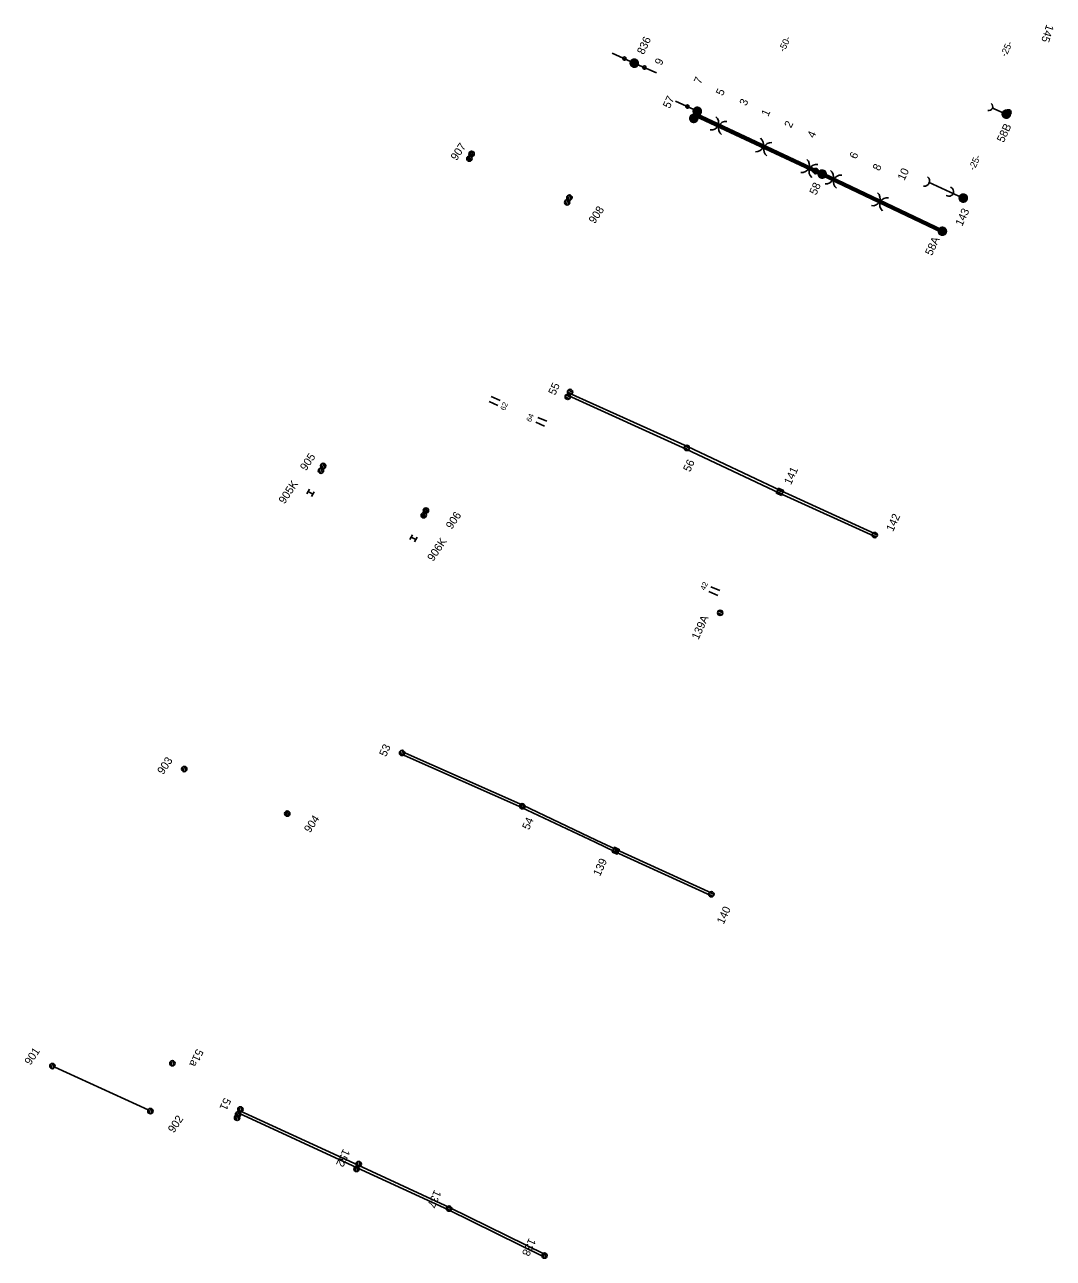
# Model space of a CAD drawing. Extents: x -595867 to -593796, y -1159595 to -1157495.
# Drawn here: x -595001.3 to -594808.6, y -1158560.8 to -1158329.6 of the extents above; entities that cross this region are included whole.
import ezdxf

# ---------------------------------------------------------------- set-up
doc = ezdxf.new("R2010")
doc.units = 0
for name, color, linetype in [('BVK_kanalizace_destova_nova', 7, 'Continuous'), ('BVK_kanalizace_jednotna_nova', 7, 'Continuous'), ('DKM19', 7, 'Continuous'), ('SO31_06_54_1-protlak', 7, 'Continuous')]:
    doc.layers.add(name, color=color, linetype=linetype)

# ---------------------------------------------------------------- blocks, each defined once
blk = doc.blocks.new('st_2t')
for points in [[(-0.0077, 0.0091), (0.0015, 0.0147), (0.0025, 0.0144), (-0.0078, 0.0082)], [(-0.0078, 0.0082), (0.0025, 0.0144), (0.0032, 0.014), (-0.0078, 0.0072)], [(-0.0078, 0.0072), (0.0032, 0.014), (0.004, 0.0135), (-0.0078, 0.0065)], [(-0.0078, 0.0065), (0.004, 0.0135), (0.0048, 0.0129), (-0.0076, 0.0056)], [(-0.0075, 0.0097), (0.0002, 0.0149), (0.0015, 0.0147), (-0.0077, 0.0091)], [(-0.0076, 0.0056), (0.0048, 0.0129), (0.0055, 0.0121), (-0.0073, 0.0044)], [(-0.0073, 0.0104), (-0.0005, 0.015), (0.0002, 0.0149), (-0.0075, 0.0097)], [(-0.0071, 0.0108), (-0.0019, 0.0148), (-0.0005, 0.015), (-0.0073, 0.0104)], [(-0.0073, 0.0044), (0.0055, 0.0121), (0.0063, 0.0109), (-0.0068, 0.0036)], [(-0.0066, 0.0115), (-0.0026, 0.0146), (-0.0019, 0.0148), (-0.0071, 0.0108)], [(-0.0068, 0.0036), (0.0063, 0.0109), (0.0067, 0.0097), (-0.006, 0.0026)], [(-0.0062, 0.0122), (-0.0035, 0.0142), (-0.0026, 0.0146), (-0.0066, 0.0115)], [(-0.0056, 0.0128), (-0.0045, 0.0137), (-0.0035, 0.0142), (-0.0062, 0.0122)], [(-0.006, 0.0026), (0.0067, 0.0097), (0.007, 0.0086), (-0.0052, 0.0018)], [(-0.0052, 0.0018), (0.007, 0.0086), (0.0071, 0.0071), (-0.0044, 0.0012)], [(-0.0044, 0.0012), (0.0071, 0.0071), (0.0069, 0.0057), (-0.0035, 0.0007)], [(-0.0035, 0.0007), (0.0069, 0.0057), (0.0066, 0.0047), (-0.0024, 0.0003)], [(-0.0024, 0.0003), (0.0066, 0.0047), (0.0061, 0.0038), (-0.0015, 0.0001)], [(-0.0015, 0.0001), (0.0061, 0.0038), (0.0055, 0.0029), (-0.0009, 0)], [(-0.0009, 0), (0.0055, 0.0029), (0.005, 0.0022), (0, 0)], [(0, 0), (0.005, 0.0022), (0.0041, 0.0015), (0.001, 0.0001)], [(0.001, 0.0001), (0.0041, 0.0015), (0.0035, 0.001), (0.0021, 0.0004)], [(0.0021, 0.0004), (0.0035, 0.001), (0.0026, 0.0006), (0.0026, 0.0005)], [(-0.0077, -0.0059), (0.0015, -0.0003), (0.0025, -0.0006), (-0.0078, -0.0068)], [(-0.0078, -0.0068), (0.0025, -0.0006), (0.0032, -0.001), (-0.0078, -0.0078)], [(-0.0078, -0.0078), (0.0032, -0.001), (0.004, -0.0015), (-0.0078, -0.0085)], [(-0.0078, -0.0085), (0.004, -0.0015), (0.0048, -0.0021), (-0.0076, -0.0094)], [(-0.0075, -0.0053), (0.0002, -0.0001), (0.0015, -0.0003), (-0.0077, -0.0059)], [(-0.0076, -0.0094), (0.0048, -0.0021), (0.0055, -0.0029), (-0.0073, -0.0106)], [(-0.0073, -0.0046), (-0.0005, 0), (0.0002, -0.0001), (-0.0075, -0.0053)], [(-0.0071, -0.0042), (-0.0019, -0.0002), (-0.0005, 0), (-0.0073, -0.0046)], [(-0.0073, -0.0106), (0.0055, -0.0029), (0.0063, -0.0041), (-0.0068, -0.0114)], [(-0.0066, -0.0035), (-0.0026, -0.0004), (-0.0019, -0.0002), (-0.0071, -0.0042)], [(-0.0068, -0.0114), (0.0063, -0.0041), (0.0067, -0.0053), (-0.006, -0.0124)], [(-0.0062, -0.0028), (-0.0035, -0.0008), (-0.0026, -0.0004), (-0.0066, -0.0035)], [(-0.0056, -0.0022), (-0.0045, -0.0013), (-0.0035, -0.0008), (-0.0062, -0.0028)], [(-0.006, -0.0124), (0.0067, -0.0053), (0.007, -0.0064), (-0.0052, -0.0132)], [(-0.0052, -0.0132), (0.007, -0.0064), (0.0071, -0.0079), (-0.0044, -0.0138)], [(-0.0044, -0.0138), (0.0071, -0.0079), (0.0069, -0.0093), (-0.0035, -0.0143)], [(-0.0035, -0.0143), (0.0069, -0.0093), (0.0066, -0.0103), (-0.0024, -0.0147)], [(-0.0024, -0.0147), (0.0066, -0.0103), (0.0061, -0.0112), (-0.0015, -0.0149)], [(-0.0015, -0.0149), (0.0061, -0.0112), (0.0055, -0.0121), (-0.0009, -0.015)], [(-0.0009, -0.015), (0.0055, -0.0121), (0.005, -0.0128), (0, -0.015)], [(0, -0.015), (0.005, -0.0128), (0.0041, -0.0135), (0.001, -0.0149)], [(0.001, -0.0149), (0.0041, -0.0135), (0.0035, -0.014), (0.0021, -0.0146)], [(0.0021, -0.0146), (0.0035, -0.014), (0.0026, -0.0144), (0.0026, -0.0145)]]:
    blk.add_lwpolyline(points, close=True)
for centre in [(-0.0004, 0.0075), (-0.0004, -0.0075)]:
    blk.add_circle(centre, 0.0075)
blk = doc.blocks.new('st_tecka')
blk.add_circle((0, 0), 0.00314)
blk = doc.blocks.new('st1k_konzola')
blk.add_line((0, 0), (0.0453, 0))
at = {"rotation": 90}
blk.add_blockref('st_tecka', (0.0205, 0), dxfattribs=at)
blk = doc.blocks.new('st_1t')
for points in [[(-0.0074, 0.0007), (0.0028, 0.0069), (0.0036, 0.0066), (-0.0075, -0.0002)], [(-0.0075, -0.0002), (0.0036, 0.0066), (0.0044, 0.006), (-0.0074, -0.001)], [(-0.0073, 0.0016), (0.0019, 0.0072), (0.0028, 0.0069), (-0.0074, 0.0007)], [(-0.0074, -0.001), (0.0044, 0.006), (0.0052, 0.0054), (-0.0072, -0.0019)], [(-0.0071, 0.0022), (0.0006, 0.0074), (0.0019, 0.0072), (-0.0073, 0.0016)], [(-0.0072, -0.0019), (0.0052, 0.0054), (0.0059, 0.0046), (-0.0069, -0.003)], [(-0.0069, 0.0029), (-0.0001, 0.0075), (0.0006, 0.0074), (-0.0071, 0.0022)], [(-0.0067, 0.0033), (-0.0015, 0.0073), (-0.0001, 0.0075), (-0.0069, 0.0029)], [(-0.0069, -0.003), (0.0059, 0.0046), (0.0067, 0.0034), (-0.0064, -0.0039)], [(-0.0063, 0.004), (-0.0022, 0.0071), (-0.0015, 0.0073), (-0.0067, 0.0033)], [(-0.0064, -0.0039), (0.0067, 0.0034), (0.0071, 0.0022), (-0.0057, -0.0049)], [(-0.0058, 0.0047), (-0.0032, 0.0068), (-0.0022, 0.0071), (-0.0063, 0.004)], [(-0.0053, 0.0053), (-0.0041, 0.0062), (-0.0032, 0.0068), (-0.0058, 0.0047)], [(-0.0057, -0.0049), (0.0071, 0.0022), (0.0074, 0.0011), (-0.0049, -0.0056)], [(-0.0049, -0.0056), (0.0074, 0.0011), (0.0075, -0.0004), (-0.004, -0.0063)], [(-0.004, -0.0063), (0.0075, -0.0004), (0.0073, -0.0017), (-0.0032, -0.0068)], [(-0.0032, -0.0068), (0.0073, -0.0017), (0.007, -0.0027), (-0.0021, -0.0072)], [(-0.0021, -0.0072), (0.007, -0.0027), (0.0065, -0.0037), (-0.0011, -0.0074)], [(-0.0011, -0.0074), (0.0065, -0.0037), (0.0059, -0.0046), (-0.0005, -0.0075)], [(-0.0005, -0.0075), (0.0059, -0.0046), (0.0054, -0.0052), (0.0004, -0.0075)], [(0.0004, -0.0075), (0.0054, -0.0052), (0.0045, -0.006), (0.0014, -0.0074)], [(0.0014, -0.0074), (0.0045, -0.006), (0.0038, -0.0064), (0.0025, -0.007)], [(0.0025, -0.007), (0.0038, -0.0064), (0.0029, -0.0069), (0.0029, -0.0069)]]:
    blk.add_lwpolyline(points, close=True)
blk.add_circle((0, 0), 0.0075)
blk = doc.blocks.new('pol_izol')
for centre, start, end in [((-0.0148, 0), 284.4047, 75.5953), ((0.0148, 0), 104.4047, 255.5953)]:
    blk.add_arc(centre, 0.0138, start, end)
blk = doc.blocks.new('st1k_1t')
blk.add_line((0, 0), (0.0453, 0))
blk.add_blockref('st_1t', (0, 0))
at = {"rotation": 90}
blk.add_blockref('st_tecka', (0.0205, 0), dxfattribs=at)
blk = doc.blocks.new('pol_delic')
for p, q in [((-0.005, -0.009), (-0.005, 0.009)), ((0.005, -0.009), (0.005, 0.009))]:
    blk.add_line(p, q)
blk = doc.blocks.new('C661_2')
at = {"layer": 'SO31_06_54_1-protlak'}
for p, q in [((-0.005, 0.0003), (-0.0003, 0.005)), ((-0.005, -0.005), (0.005, 0.005)), ((0.0003, -0.005), (0.005, -0.0003))]:
    blk.add_line(p, q, dxfattribs=at)
blk.add_lwpolyline([(-0.005, 0.005), (0.005, 0.005), (0.005, -0.005), (-0.005, -0.005)], close=True, dxfattribs=at)
blk.add_lwpolyline([(-0.005, 0.005), (0.005, 0.005), (0.005, -0.005), (-0.005, -0.005), (-0.005, 0.005)], dxfattribs=at)

msp = doc.modelspace()

# ---------------------------------------------------------------- linework, layer by layer
at = {"layer": 'BVK_kanalizace_destova_nova'}
for p, q in [((-594851.87, -1158357.6), (-594875.56, -1158346.51)), ((-594817.37, -1158346.37), (-594820.1, -1158345.19)), ((-594829.35, -1158368.32), (-594851.87, -1158357.6)), ((-594825.43, -1158362.1), (-594831.94, -1158359.15))]:
    msp.add_line(p, q, dxfattribs=at)
for centre, radius, start, end in [((-594820.62, -1158344.99), 0.706, 251.6408, 56.1676), ((-594832.73, -1158358.89), 0.992, 262.1306, 51.1807), ((-594828.12, -1158360.87), 0.882, 234.6975, 70.6759)]:
    msp.add_arc(centre, radius, start, end, dxfattribs=at)
at = {"layer": 'BVK_kanalizace_jednotna_nova'}
for p, q in [((-594875.89, -1158347.44), (-594876.05, -1158346.54)), ((-594875.52, -1158347.39), (-594875.69, -1158346.47)), ((-594875.46, -1158346.54), (-594875.62, -1158345.64)), ((-594875.09, -1158346.48), (-594875.26, -1158345.57)), ((-594817.08, -1158346.53), (-594817.24, -1158345.63)), ((-594816.71, -1158346.47), (-594816.88, -1158345.56)), ((-594917.6, -1158354.3), (-594917.9, -1158353.46)), ((-594917.24, -1158354.2), (-594917.56, -1158353.31)), ((-594918.04, -1158355.21), (-594918.33, -1158354.36)), ((-594917.67, -1158355.11), (-594917.99, -1158354.21)), ((-594853.21, -1158357.51), (-594853.37, -1158356.61)), ((-594852.84, -1158357.46), (-594853.01, -1158356.54)), ((-594899.72, -1158363.42), (-594900.01, -1158362.57)), ((-594899.35, -1158363.32), (-594899.67, -1158362.42)), ((-594899.28, -1158362.51), (-594899.58, -1158361.67)), ((-594898.92, -1158362.41), (-594899.24, -1158361.52)), ((-594829.46, -1158368.83), (-594829.62, -1158367.93)), ((-594829.09, -1158368.77), (-594829.26, -1158367.86)), ((-594899.19, -1158399.71), (-594900.04, -1158399.37)), ((-594899.04, -1158399.37), (-594899.9, -1158399.02)), ((-594898.76, -1158398.79), (-594899.61, -1158398.45)), ((-594898.61, -1158398.45), (-594899.47, -1158398.1)), ((-594876.88, -1158409.27), (-594877.73, -1158408.93)), ((-594876.73, -1158408.93), (-594877.59, -1158408.58)), ((-594945.85, -1158413.71), (-594946.15, -1158412.87)), ((-594945.49, -1158413.61), (-594945.81, -1158412.72)), ((-594945.42, -1158412.8), (-594945.73, -1158411.96)), ((-594945.06, -1158412.7), (-594945.39, -1158411.81)), ((-594948.41, -1158417.55), (-594947.92, -1158416.68)), ((-594948.17, -1158417.12), (-594947.29, -1158417.6)), ((-594947.54, -1158418.04), (-594947.05, -1158417.17)), ((-594859.12, -1158416.9), (-594860.43, -1158417.42)), ((-594859.61, -1158416.69), (-594860.23, -1158416.94)), ((-594859.33, -1158417.39), (-594859.95, -1158417.63)), ((-594926.16, -1158421.14), (-594926.47, -1158420.3)), ((-594925.8, -1158421.04), (-594926.13, -1158420.15)), ((-594926.59, -1158422.05), (-594926.89, -1158421.21)), ((-594926.23, -1158421.95), (-594926.55, -1158421.05)), ((-594929.11, -1158426.06), (-594928.62, -1158425.19)), ((-594841.67, -1158425.61), (-594842.52, -1158425.27)), ((-594841.52, -1158425.27), (-594842.38, -1158424.92)), ((-594928.87, -1158425.63), (-594927.99, -1158426.11)), ((-594928.24, -1158426.55), (-594927.75, -1158425.68)), ((-594870.63, -1158440.18), (-594871.48, -1158439.84)), ((-594870.48, -1158439.84), (-594871.34, -1158439.49)), ((-594930.7, -1158466.58), (-594930.86, -1158465.68)), ((-594930.33, -1158466.52), (-594930.49, -1158465.61)), ((-594971.41, -1158469.62), (-594971.72, -1158468.76)), ((-594971.05, -1158469.49), (-594971.37, -1158468.62)), ((-594908.18, -1158476.56), (-594908.34, -1158475.66)), ((-594907.81, -1158476.5), (-594907.97, -1158475.59)), ((-594952.13, -1158477.96), (-594952.44, -1158477.1)), ((-594951.77, -1158477.83), (-594952.09, -1158476.96)), ((-594872.27, -1158492.94), (-594873.12, -1158492.6)), ((-594872.12, -1158492.6), (-594872.98, -1158492.25)), ((-594996.12, -1158525.28), (-594996.43, -1158524.42)), ((-594995.76, -1158525.15), (-594996.08, -1158524.28)), ((-594973.72, -1158524.74), (-594973.88, -1158523.84)), ((-594973.35, -1158524.68), (-594973.51, -1158523.77)), ((-594977.76, -1158533.72), (-594978.07, -1158532.86)), ((-594977.4, -1158533.59), (-594977.72, -1158532.72)), ((-594961.61, -1158534.96), (-594961.77, -1158534.06)), ((-594961.41, -1158534.3), (-594961.57, -1158533.4)), ((-594961.24, -1158534.9), (-594961.41, -1158533.99)), ((-594961.04, -1158534.25), (-594961.2, -1158533.33)), ((-594960.99, -1158533.38), (-594961.15, -1158532.48)), ((-594960.62, -1158533.32), (-594960.79, -1158532.41)), ((-594938.82, -1158543.62), (-594938.98, -1158542.72)), ((-594938.45, -1158543.56), (-594938.61, -1158542.65)), ((-594939.23, -1158544.54), (-594939.39, -1158543.64)), ((-594938.86, -1158544.49), (-594939.03, -1158543.57)), ((-594921.89, -1158551.98), (-594922.05, -1158551.08)), ((-594921.52, -1158551.93), (-594921.69, -1158551.01)), ((-594904.01, -1158560.79), (-594904.17, -1158559.89)), ((-594903.64, -1158560.73), (-594903.81, -1158559.82))]:
    msp.add_line(p, q, dxfattribs=at)
for points in [[(-594853.21, -1158357.26), (-594875.67, -1158346.74)], [(-594852.99, -1158356.8), (-594875.45, -1158346.28)], [(-594829.46, -1158368.57), (-594853.21, -1158357.26)], [(-594829.24, -1158368.12), (-594852.99, -1158356.8)], [(-594877.33, -1158409.15), (-594899.45, -1158399.12)], [(-594877.12, -1158408.69), (-594899.25, -1158398.66)], [(-594859.88, -1158417.39), (-594877.34, -1158409.15)], [(-594859.67, -1158416.93), (-594877.12, -1158408.69)], [(-594859.52, -1158417.82), (-594860.44, -1158417.42), (-594860.04, -1158416.5), (-594859.12, -1158416.9), (-594859.52, -1158417.82)], [(-594842.12, -1158425.49), (-594859.88, -1158417.39)], [(-594841.92, -1158425.03), (-594859.68, -1158416.93)], [(-594908.17, -1158476.31), (-594930.69, -1158466.33)], [(-594907.97, -1158475.85), (-594930.49, -1158465.87)], [(-594894.42, -1158482.84), (-594908.18, -1158476.3)], [(-594894.23, -1158482.42), (-594907.96, -1158475.85)], [(-594890.66, -1158484.64), (-594894.42, -1158482.84)], [(-594890.45, -1158484.19), (-594894.23, -1158482.42)], [(-594872.73, -1158492.81), (-594890.65, -1158484.65)], [(-594872.52, -1158492.36), (-594890.45, -1158484.19)], [(-594978.14, -1158532.99), (-594995.65, -1158524.99)], [(-594939.02, -1158543.83), (-594961.19, -1158533.6)], [(-594938.81, -1158543.37), (-594960.98, -1158533.14)], [(-594921.68, -1158551.27), (-594938.82, -1158543.37)], [(-594921.89, -1158551.73), (-594939.02, -1158543.83)], [(-594904.01, -1158560.53), (-594921.89, -1158551.72)], [(-594903.79, -1158560.08), (-594921.67, -1158551.28)]]:
    msp.add_lwpolyline(points, dxfattribs=at)
msp.add_lwpolyline([(-594859.52, -1158417.82), (-594860.44, -1158417.42), (-594860.04, -1158416.5), (-594859.12, -1158416.9)], close=True, dxfattribs=at)
for centre in [(-594875.78, -1158346.96), (-594875.78, -1158346.96), (-594875.35, -1158346.05), (-594875.35, -1158346.05), (-594816.97, -1158346.05), (-594816.97, -1158346.05), (-594917.55, -1158353.81), (-594917.55, -1158353.81), (-594917.97, -1158354.71), (-594917.97, -1158354.71), (-594853.1, -1158357.03), (-594853.1, -1158357.03), (-594899.65, -1158362.92), (-594899.65, -1158362.92), (-594899.23, -1158362.02), (-594899.23, -1158362.02), (-594829.35, -1158368.35), (-594829.35, -1158368.35), (-594899.54, -1158399.36), (-594899.54, -1158399.36), (-594899.11, -1158398.44), (-594899.11, -1158398.44), (-594877.23, -1158408.92), (-594877.23, -1158408.92), (-594945.79, -1158413.21), (-594945.79, -1158413.21), (-594945.37, -1158412.31), (-594945.37, -1158412.31), (-594926.11, -1158420.65), (-594926.11, -1158420.65), (-594926.53, -1158421.55), (-594926.53, -1158421.55), (-594842.02, -1158425.26), (-594842.02, -1158425.26), (-594870.98, -1158439.83), (-594870.98, -1158439.83), (-594930.59, -1158466.1), (-594930.59, -1158466.1), (-594971.38, -1158469.12), (-594971.38, -1158469.12), (-594908.07, -1158476.08), (-594908.07, -1158476.08), (-594952.1, -1158477.46), (-594952.1, -1158477.46), (-594872.62, -1158492.59), (-594872.62, -1158492.59), (-594996.09, -1158524.78), (-594996.09, -1158524.78), (-594973.61, -1158524.25), (-594973.61, -1158524.25), (-594977.73, -1158533.22), (-594977.73, -1158533.22), (-594961.5, -1158534.48), (-594961.5, -1158534.48), (-594961.3, -1158533.82), (-594961.3, -1158533.82), (-594960.88, -1158532.9), (-594960.88, -1158532.9), (-594938.71, -1158543.14), (-594938.71, -1158543.14), (-594939.12, -1158544.06), (-594939.12, -1158544.06), (-594921.78, -1158551.5), (-594921.78, -1158551.5), (-594903.9, -1158560.31), (-594903.9, -1158560.31)]:
    msp.add_circle(centre, 0.5, dxfattribs=at)

# ---------------------------------------------------------------- block references
at = {"layer": 'BVK_kanalizace_destova_nova'}
for name, p, xscale, yscale, rotation in [('st1k_1t', (-594887.07, -1158336.82), 100, 100, 155.56081187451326), ('st1k_1t', (-594887.07, -1158336.82), 100, 100, -23.3948220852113), ('st1k_konzola', (-594875.26, -1158345.82), 100, 100.00000000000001, 155.36185585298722), ('st_2t', (-594875.56, -1158346.51), 100, 100, -26.108329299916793), ('pol_izol', (-594871.28, -1158348.53), 100, 100.00000000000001, -22.292826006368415), ('st_1t', (-594817.37, -1158346.37), 100.00000000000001, 100, 1), ('pol_izol', (-594862.83, -1158352.55), 99.99999999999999, 100.00000000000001, -20.35128171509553), ('pol_izol', (-594854.28, -1158356.54), 100, 100, -24.588852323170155), ('st_1t', (-594851.87, -1158357.6), 100.00000000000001, 100, 1), ('pol_izol', (-594849.75, -1158358.61), 99.99999999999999, 100.00000000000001, -21.721266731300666), ('pol_izol', (-594841.04, -1158362.78), 100, 100, -24.588852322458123), ('st_1t', (-594825.43, -1158362.1), 100.00000000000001, 100, 1), ('st_1t', (-594829.35, -1158368.32), 100.00000000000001, 100, 1), ('pol_delic', (-594913.26, -1158400.12), 100, 100.00000000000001, 65.41114767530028), ('pol_delic', (-594904.51, -1158404.03), 99.99999999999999, 100.00000000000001, 66.55612357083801), ('pol_delic', (-594872.08, -1158435.75), 100, 99.99999999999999, 67.04622168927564)]:
    msp.add_blockref(name, p, dxfattribs=dict(at, xscale=xscale, yscale=yscale, rotation=rotation))
at = {"layer": 'BVK_kanalizace_jednotna_nova', "xscale": 99.99954548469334, "yscale": 99.99954548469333, "rotation": 65.45341260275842}
msp.add_blockref('C661_2', (-594890.55, -1158484.42), dxfattribs=at)

# ---------------------------------------------------------------- texts
at = {"layer": 'BVK_kanalizace_destova_nova'}
for s, height, rotation, p in [('836', 1.5, 65.0264, (-594885.3, -1158335.32)), ('-50-', 1.25, 65.0264, (-594858.96, -1158334.83)), ('-25-', 1.25, 65.0264, (-594817.41, -1158335.75)), ('9', 1.5, 65.0264, (-594881.98, -1158337.34)), ('7', 1.5, 65.0264, (-594874.64, -1158340.85)), ('5', 1.5, 65.0264, (-594870.51, -1158343.04)), ('57', 1.5, 65.0264, (-594880.45, -1158345.42)), ('3', 1.5, 65.0264, (-594866.11, -1158344.94)), ('1', 1.5, 65.0264, (-594862, -1158346.92)), ('2', 1.5, 65.0264, (-594857.69, -1158349.09)), ('58B', 1.5, 65.0264, (-594817.87, -1158351.81)), ('4', 1.5, 65.0264, (-594853.39, -1158350.99)), ('6', 1.5, 65.0264, (-594845.5, -1158354.91)), ('8', 1.5, 65.0264, (-594841.15, -1158357.13)), ('-25-', 1.25, 65.0264, (-594823.37, -1158357.04)), ('10', 1.5, 65.0264, (-594836.48, -1158358.95)), ('58', 1.5, 65.0264, (-594853, -1158361.65)), ('143', 1.5, 65.0264, (-594825.65, -1158367.49)), ('58A', 1.5, 65.0264, (-594831.32, -1158373.01)), ('62', 1, 66.0946, (-594911.32, -1158402.03)), ('64', 1, 66.0946, (-594906.46, -1158404.17)), ('42', 1, 66.0946, (-594873.84, -1158435.7))]:
    msp.add_text(s, height=height, rotation=rotation, dxfattribs=at).set_placement(p)
at = {"layer": 'BVK_kanalizace_jednotna_nova'}
for s, rotation, p in [('907', 56, (-594920.38, -1158355.2)), ('908', 56, (-594894.51, -1158367.03)), ('55', 65.4024, (-594901.9, -1158399.17)), ('905', 56, (-594948.59, -1158413.34)), ('56', 65.4024, (-594876.64, -1158413.55)), ('141', 65.4024, (-594857.73, -1158415.96)), ('905K', 56, (-594952.61, -1158419.54)), ('906', 56, (-594921.28, -1158424.29)), ('142', 65.4024, (-594838.6, -1158424.72)), ('906K', 56, (-594924.75, -1158430.31)), ('139A', 65.4024, (-594875.06, -1158444.98)), ('53', 65.4024, (-594933.59, -1158466.91)), ('903', 56, (-594975.35, -1158470.26)), ('904', 56, (-594947.84, -1158481.18)), ('54', 65.4024, (-594906.81, -1158480.63)), ('139', 65.4024, (-594893.51, -1158489.33)), ('140', 65.4024, (-594870.34, -1158498.32)), ('901', 56, (-595000.22, -1158524.72)), ('902', 56, (-594973.35, -1158537.42))]:
    msp.add_text(s, height=1.5, rotation=rotation, dxfattribs=at).set_placement(p)
at = {"layer": 'DKM19'}
for s, rotation, p in [('145', 252.4875, (-594809.84, -1158329.46)), ('51a', 245.2949, (-594969.08, -1158521.45)), ('51', 245.4237, (-594963.91, -1158530.59)), ('152', 245.3801, (-594941.6, -1158540.18)), ('137', 245.4545, (-594924.51, -1158547.87)), ('138', 245.3417, (-594906.78, -1158556.91))]:
    msp.add_text(s, height=1.5, rotation=rotation, dxfattribs=at).set_placement(p)

doc.saveas('drawing.dxf')
